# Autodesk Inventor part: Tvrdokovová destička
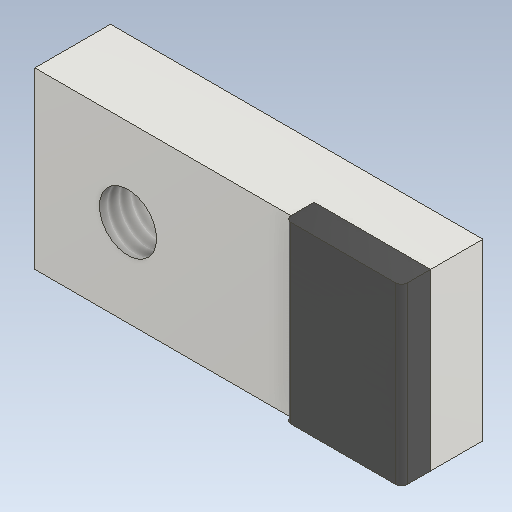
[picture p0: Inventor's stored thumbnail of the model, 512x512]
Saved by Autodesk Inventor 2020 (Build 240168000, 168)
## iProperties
Created: 2025-03
Part Number: Tvrdokovová destička
Material: Ocel
Document SubType Name: Modeling
Designer: doma
Density: 7.85 g/cm^3
Appearance: Ocel
Mass: 24.0992 g
Surface Area: 20.1178 cm^2
Volume: 3.06997 cm^3
Author: doma
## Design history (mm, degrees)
sketch "Náčrt1"
  geometry: L1 (-16, -7.5)-(16, -7.5); L2 (16, -7.5)-(16, 7.5); L3 (16, 7.5)-(-16, 7.5); L4 (-16, 7.5)-(-16, -7.5); L5 (-16, -7.5)-(16, 7.5); L6 (16, -7.5)-(-16, 7.5); 1 further point
  constraints: 12 end point, 2 midpoint, 2 parallel, 1 horizontal, 1 perpendicular
  dimensions: "d0" = 32 distance of L3.end L2.end; "d1" = 15 distance of L2.end L1.end
extrude "Vysunutí1" new body sketch "Náčrt1" stored distance "d2" = 6.5; taper "d3" = 0 deg
sketch "Náčrt3"
  geometry: L1 (-16, 7.5)-(-16, -7.5) reference; 2 further points
  dimensions: "d9" = 8 distance from line of point (-8, 0) L1
hole "Díra1" sketch "Náčrt3" at (-8, 0) diameter "d10" = 4.917; stored, may be unused: countersink angle "d14" = 90 deg, drill point angle "d16" = 118 deg; dims "d11" = 12, "d12" = 4, "d13" = 2, "d15" = 17.1
sketch "Náčrt4"
  geometry: L1 (0, 0)-(32, 0) reference; L2 (32, 0)-(32, -0.5); L3 (32, -0.5)-(22, -0.5); L4 (22, -0.5)-(22, 0); L5 (22, 0)-(22, 2); L6 (22, 2)-(32, 2); L7 (32, 6.5)-(32, 0) reference; 1 further point
  constraints: 10 end point, 3 perpendicular, 2 point on line, 1 vertical
  dimensions: "d17" = 0.5 distance of L1.end L2.end; "d18" = 10 distance of L2.end L3.end; "d19" = 2 distance of L4.end L5.end
extrude "Vysunutí3" cut sketch "Náčrt4" stored distance "d20" = 0.5; taper "d21" = 0 deg
extrude "Vysunutí4" new body sketch "Náčrt4" stored distance "d22" = 0.5; taper "d23" = 0 deg
fillet "Zaoblení2" dims "d24" = 0.5
node "Těleso1"
node "Těleso2"
